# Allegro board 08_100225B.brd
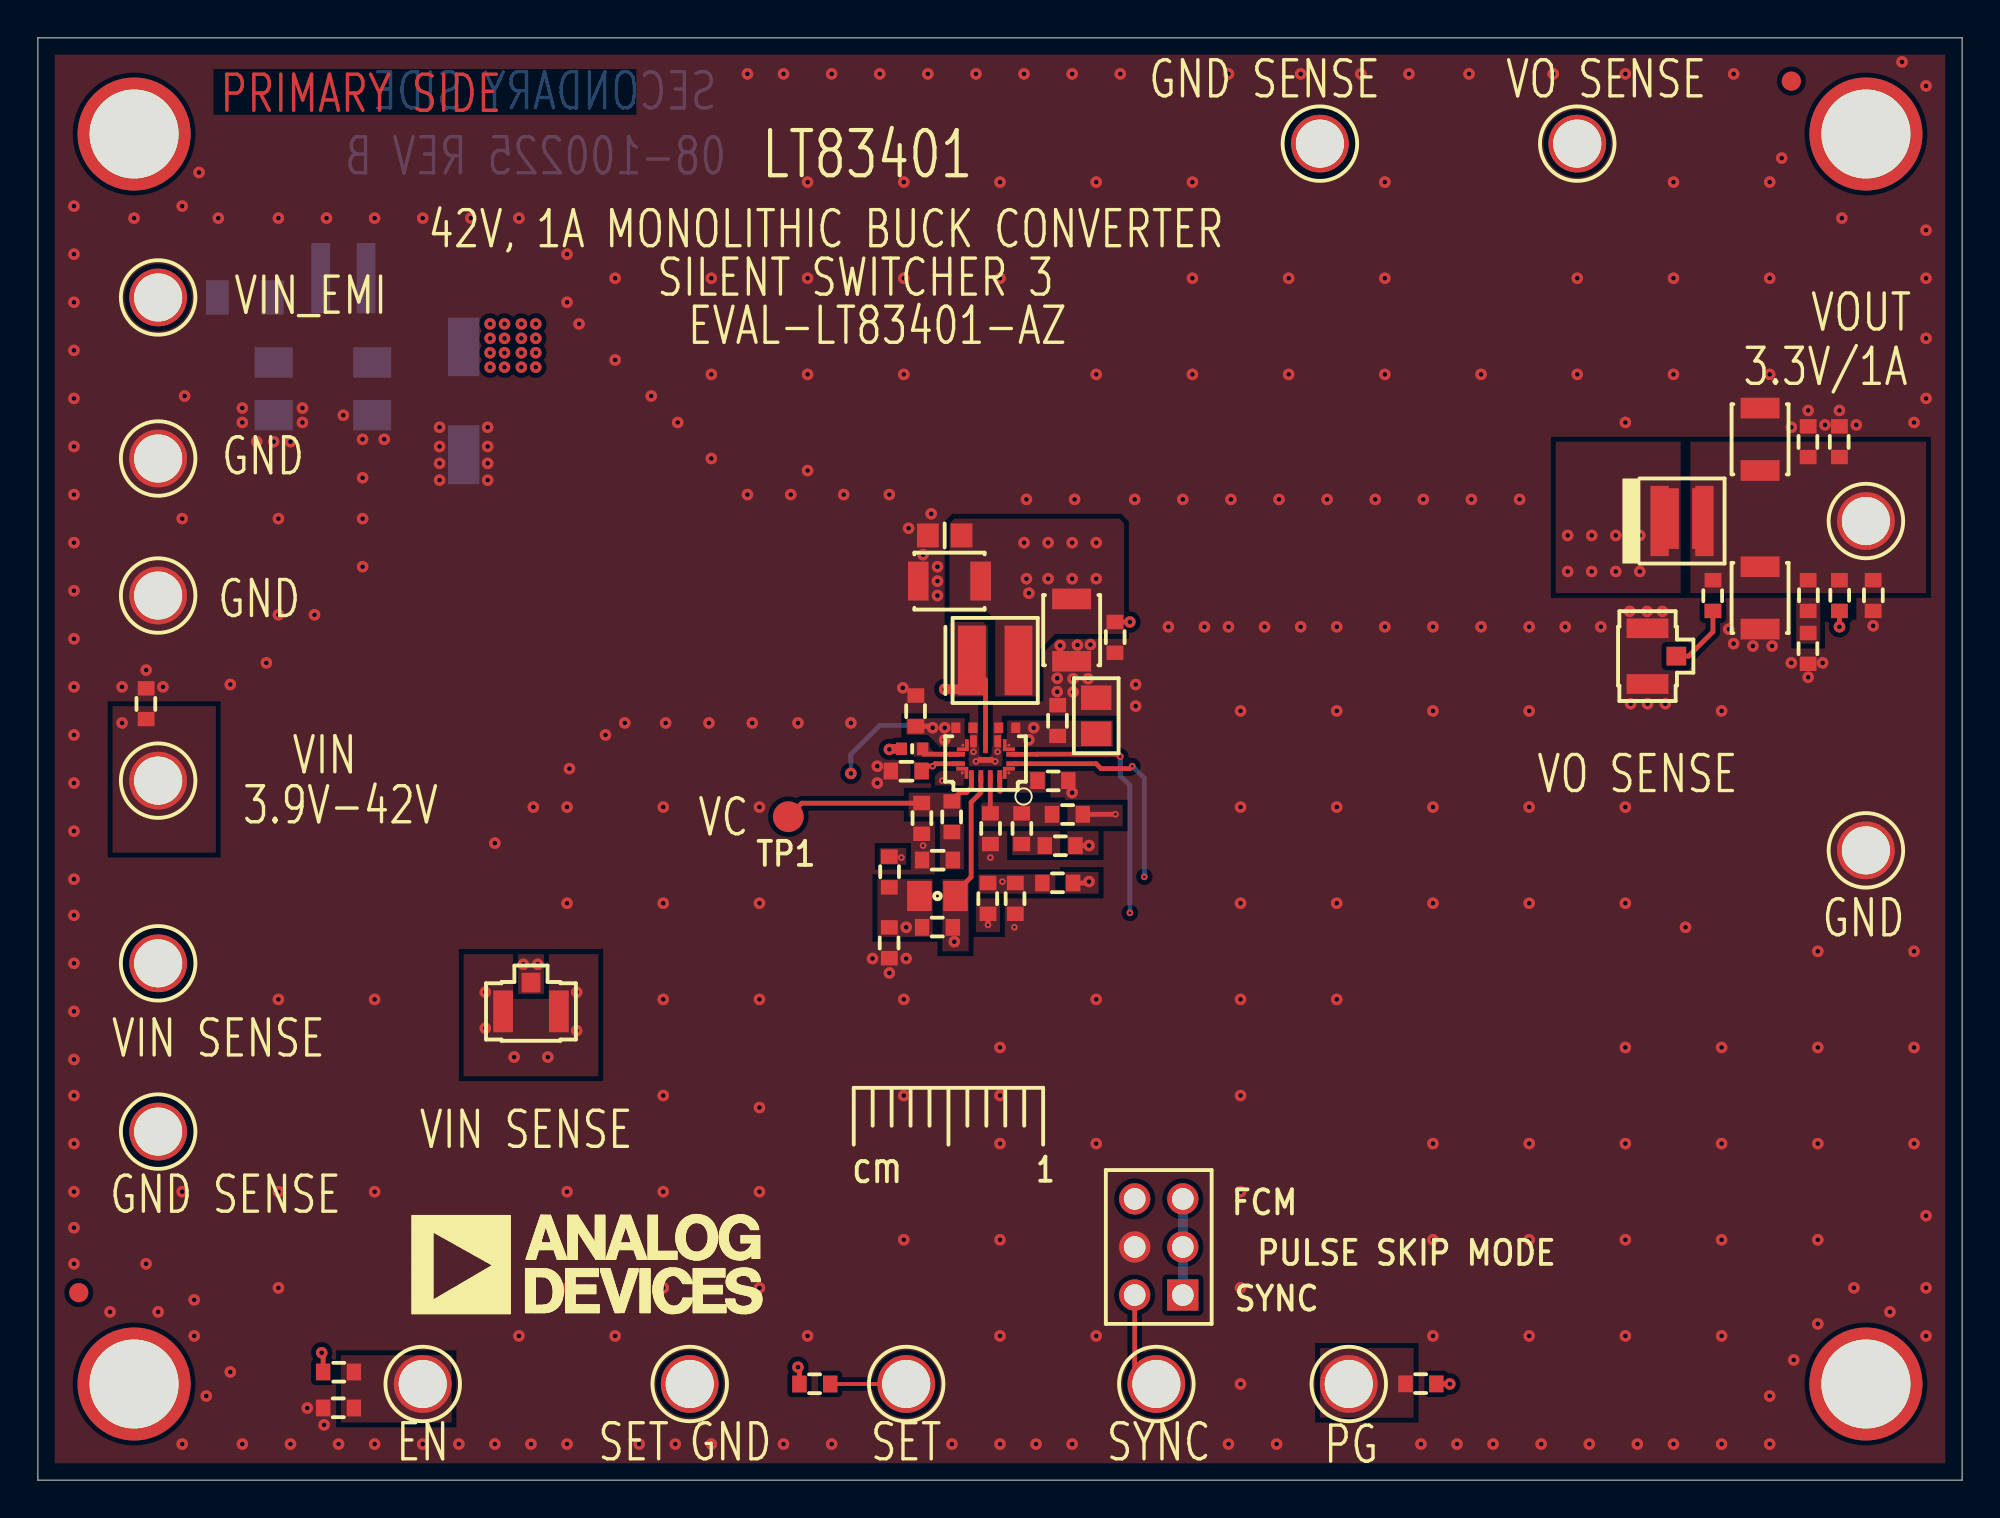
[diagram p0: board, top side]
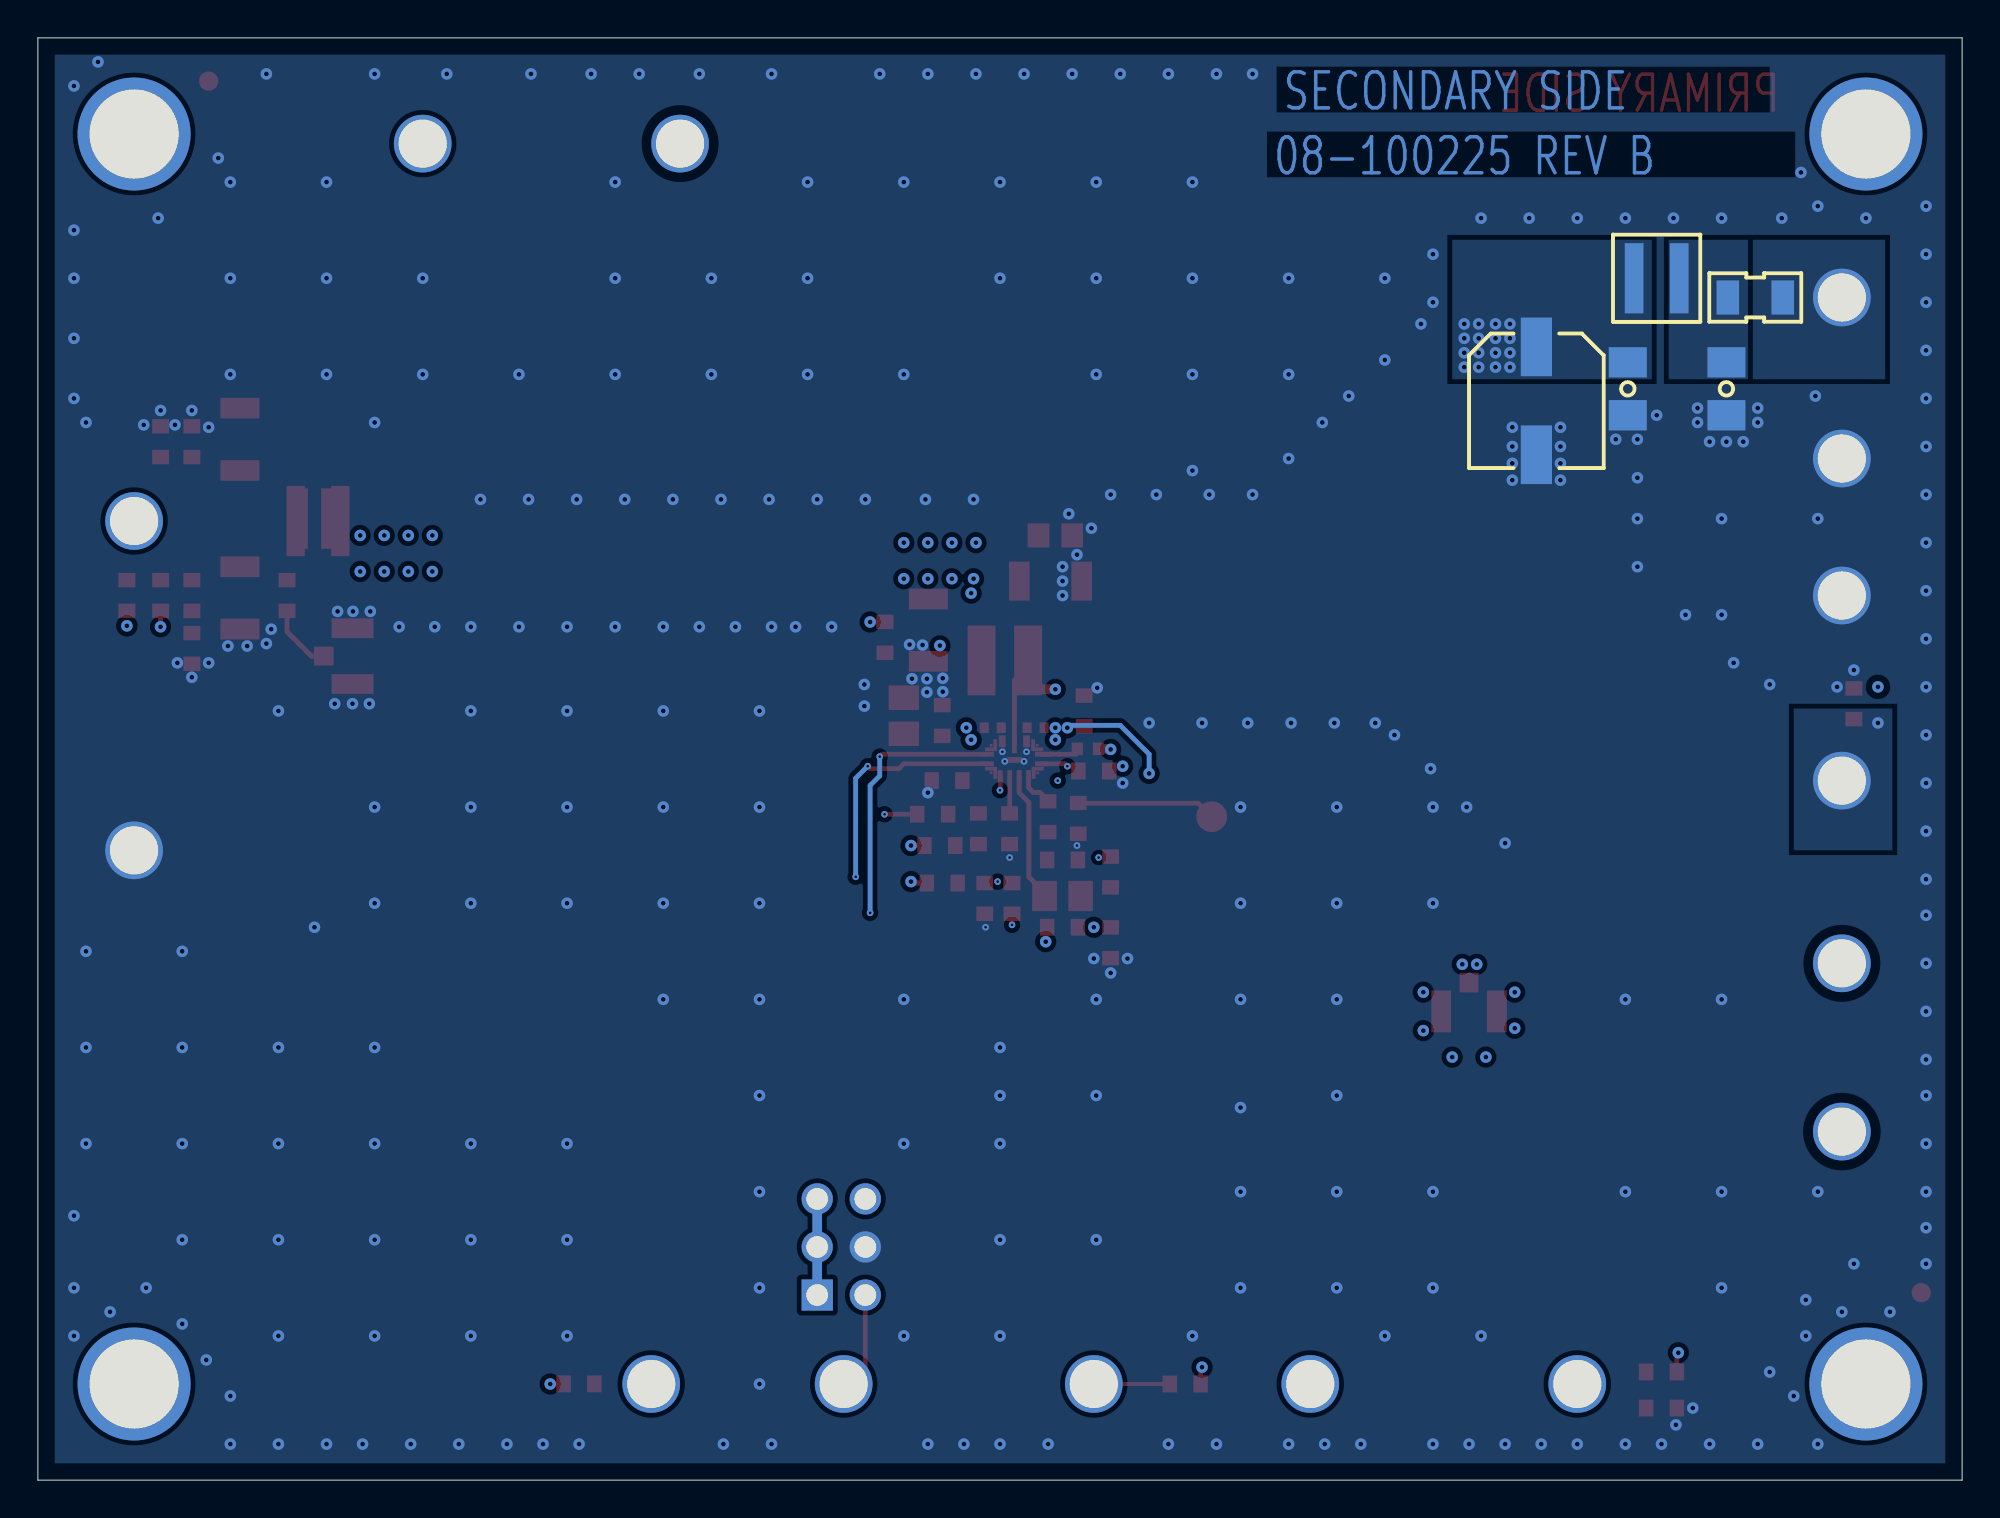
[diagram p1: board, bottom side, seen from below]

Outline 101.6 x 76.2 mm; copper layers: TOP, LAYER_2, LAYER_3, BOTTOM. Coordinates in mm from the lower left corner of the outline.
Outline path: 0,76.2 0,0 101.6,0 101.6,76.2 0,76.2

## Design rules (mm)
constraint set DEFAULT: min track width 0.203

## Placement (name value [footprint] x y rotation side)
C1  1uF  [C1206H71]  17.65 57.66 270 bottom
C2  2.2uF  [C0603]  5.71 41.02 90 top
C4  22uF  [CPLSMSQ260H315]  22.48 57.02 270 bottom
C5  4.7uF  [C0805H53]  55.88 40.39 90 top
C6  4.7uF  [C1206H71]  12.45 57.66 270 bottom
C7  1UF  [C0402]  51.18 39.75 180 top
C8  4700pF  [C0603]  47.5 32.77 180 top
C9  1UF  [C0402]  48.92 39.75 0 top
C10  2.2uF  [C0603]  56.87 44.53 270 top
C11  82PF  [C0603]  46.67 34.96 270 top
C12  1uF  [C0603]  45.85 37.47 180 top
C13  0.1uF  [C0402#2]  46.16 38.64 0 top
C14  1uF  [C0805H60]  47.5 30.86 180 top
C15  22uF  [C1210H106]  48.13 47.5 180 top
C16  22uF  [C1210H106]  54.58 44.91 270 top
C18  TBD0805  [C0805]  47.88 49.91 180 top
C19  22uF  [C1210H106]  90.93 54.99 90 top
C20  22uF  [C1210H106]  90.93 46.61 270 top
C21  2.2uF  [C0603]  96.9 46.74 270 top
C22  TBD0603  [C0603]  93.47 54.86 90 top
C23  TBD0603  [C0603]  95.12 54.86 90 top
C24  TBD0603  [C0603]  93.47 46.74 270 top
C25  1uF  [C0603]  46.35 40.64 90 top
C26  1uF  [C0603]  53.85 40.13 90 top
E1  2501-2-00-80-00-00-07-0  [CNMILLMAX2501]  6.35 62.48 90 top
E2  2501-2-00-80-00-00-07-0  [CNMILLMAX2501]  6.35 53.98 90 top
E3  2501-2-00-80-00-00-07-0  [CNMILLMAX2501]  6.35 27.3 90 top
E4  2501-2-00-80-00-00-07-0  [CNMILLMAX2501]  6.35 18.41 90 top
E5  2501-2-00-80-00-00-07-0  [CNMILLMAX2501]  59.05 5.08 0 top
E6  2501-2-00-80-00-00-07-0  [CNMILLMAX2501]  6.35 36.96 0 top
E7  2501-2-00-80-00-00-07-0  [CNMILLMAX2501]  6.35 46.74 0 top
E8  2501-2-00-80-00-00-07-0  [CNMILLMAX2501]  20.32 5.08 0 top
E9  2501-2-00-80-00-00-07-0  [CNMILLMAX2501]  69.22 5.08 0 top
E10  2501-2-00-80-00-00-07-0  [CNMILLMAX2501]  81.28 70.61 90 top
E11  2501-2-00-80-00-00-07-0  [CNMILLMAX2501]  67.69 70.61 270 top
E12  2501-2-00-80-00-00-07-0  [CNMILLMAX2501]  96.52 50.67 0 top
E13  2501-2-00-80-00-00-07-0  [CNMILLMAX2501]  96.52 33.27 0 top
E14  2501-2-00-80-00-00-07-0  [CNMILLMAX2501]  45.85 5.08 0 top
E15  2501-2-00-80-00-00-07-0  [CNMILLMAX2501]  34.42 5.08 0 top
FB1  800OHM AT 100MHZ  [L1206H71]  10.92 62.48 0 bottom
J5  RSP-122811-01  [CNSMASQ102H56]  26.04 24.77 180 top
J6  RSP-122811-01  [CNSMASQ102H56]  84.99 43.54 90 top
JP1  TSW-103-07-F-D  [CNSAMTEC2X3H330LD36]  60.45 9.78 90 top
L1  2.2UH  [LSMSQ157H83]  50.55 43.31 0 top
L2  4.7UH  [LSMSQ161H83]  16.13 63.5 0 bottom
L3  2.2UH  [LSMSQ157H122]  86.81 50.67 0 top
NOREF  -  []  0 76.2 0 top
NOREF#2  -  [unnamed#2]  5.08 71.12 0 top
NOREF#3  -  []  49.07 88.54 0 top
NOREF#4  -  []  0.64 75.56 270 top
NOREF#5  -  []  46.23 21.97 0 top
NOREF#6  -  [unnamed#2]  96.52 5.08 0 top
NOREF#7  -  []  -115.44 -203.45 0 top
NOREF#8  -  []  -73.41 -186.18 0 top
NOREF#9  -  [unnamed#2]  5.08 5.08 0 top
NOREF#10  -  []  0 0 90 top
NOREF#11  -  []  -73.41 -186.18 0 top
NOREF#12  -  []  100.97 75.56 180 top
NOREF#13  -  []  330.42 228.99 0 top
NOREF#14  -  []  337.44 165.48 0 top
NOREF#15  -  []  0.64 0.64 0 top
NOREF#16  -  [unnamed#2]  92.58 73.91 0 top
NOREF#17  -  []  165.48 219.71 0 top
NOREF#18  -  [unnamed#2]  2.16 9.91 0 top
NOREF#19  -  []  100.97 0.64 90 top
NOREF#20  -  [unnamed#2]  96.52 71.12 0 top
NOREF#21  -  []  262.51 65.15 0 top
R1  1K  [R0603]  48.26 35.05 270 top
R2  TBD0603  [R0603]  41.02 5.08 180 top
R3  100K  [R0603]  15.88 5.71 0 top
R4  47.5K  [R0603]  53.59 36.96 0 top
R5  TBD0603  [R0603]  15.88 3.81 180 top
R6  33.2K  [R0603]  47.5 29.21 180 top
R7  0  [R0603]  51.94 34.42 90 top
R8  0.001  [R0612]  87 50.8 0 top
R9  TBD0603  [R0603]  54.36 35.18 0 top
R10  280K  [R0603]  53.85 31.55 180 top
R11  49.9K  [R0603]  51.61 30.73 270 top
R12  100K  [R0603]  73.03 5.09 180 top
R13  TBD0603  [R0603]  93.47 43.94 270 top
R14  0  [R0603]  53.98 33.53 0 top
R15  TBD0603  [R0603]  50.29 34.42 90 top
R16  TBD0603  [R0603]  95.12 46.74 90 top
R17  TBD0603  [R0603]  44.96 32.13 90 top
R18  0  [R0603]  44.96 28.39 270 top
R19  TBD0603  [R0603]  50.16 30.73 270 top
R22  0  [R0603]  88.44 46.74 270 top
TP1  NCTARGET_PAD_C62AU  [TPSMC62]  39.62 35.05 0 top
U1  LT83401RUDB#TRPBF  [QFN15_CP-15-1]  50.04 38.1 180 top

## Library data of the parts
C1 = CAP: Tolerance: 10; User Part Number: UPN; alternate symbols: (C1206H71); part number: CAP_SM-1UF,50V,10,E030213,C1206H71; tolerance: 10
C2 = CAP: Tolerance: 10; User Part Number: UPN; alternate symbols: (C0603); part number: CAP_SM-2.2UF,50V,10,E024995,C0603; tolerance: 10
C4 = CAPP: Tolerance: 20; User Part Number: UPN; alternate symbols: (CPLSMSQ260H315); part number: CAPP_SM-22UF,63V,20,E033596,CPLSMSQ260H315; tolerance: 20
C5 = CAP: Tolerance: 10; User Part Number: UPN; alternate symbols: (C0805H53); part number: CAP_SM-4.7UF,50V,10,E028468,C0805H53; tolerance: 10
C6 = CAP: Tolerance: 10; User Part Number: UPN; alternate symbols: (C1206H71); part number: CAP_SM-4.7UF,50V,10,E026699,C1206H71; tolerance: 10
C7 C9 = CAP: User Part Number: UPN; Tolerance: 10; alternate symbols: (C0402L); part number: CAP_SM-1UF,50V,10,E064438,C0402; tolerance: 10
C8 = CAP: Tolerance: 10; User Part Number: UPN; alternate symbols: (C0603); part number: CAP_SM-4700PF,50V,10,E000427,C0603; tolerance: 10
C10 C21 = CAP: Tolerance: 10; User Part Number: UPN; alternate symbols: (C0603); part number: CAP_SM-2.2UF,25V,10,E031885,C0603; tolerance: 10
C11 = CAP: Tolerance: 5; User Part Number: UPN; alternate symbols: (C0603); part number: CAP_SM-82PF,50V,5,E042666,C0603; tolerance: 5
C12 = CAP: Tolerance: 10; User Part Number: UPN; alternate symbols: (C0603); part number: CAP_SM-1UF,25V,10,E033832,C0603; tolerance: 10
C13 = CAP: Tolerance: 10; User Part Number: UPN; alternate symbols: (C0402); part number: CAP_SM-0.1UF,50V,10,E028943,C0402; tolerance: 10
C14 = CAP: Tolerance: 10; User Part Number: UPN; alternate symbols: (C0805H60); part number: CAP_SM-1UF,50V,10,E030886,C0805H60; tolerance: 10
C15 C16 C19 C20 = CAP: Tolerance: 10; User Part Number: UPN; alternate symbols: (C1210H106); part number: CAP_SM-22UF,25V,10,E025745,C1210H106; tolerance: 10
C18 = CAP: User Part Number: UPN; alternate symbols: (C0805); part number: CAP_SM-TBD0805,TBD0805,TBD0805,E000383,C0805
C22-C24 = CAP: User Part Number: UPN; alternate symbols: (C0603); part number: CAP_SM-TBD0603,TBD0603,TBD0603,E000382,C0603
C25 C26 = CAP: Tolerance: 10; User Part Number: UPN; alternate symbols: (C0603); part number: CAP_SM-1UF,50V,10,E023087,C0603; tolerance: 10
E1-E15 = CNTP1P: User Part Number: UPN; Tolerance: N/A; alternate symbols: (CNMILLMAX2501); part number: CNTP1P_TH-2501-2-00-80-00-00-07-0,E031108,CNMILLMAX2501; tolerance: N/A
FB1 = FERRITE: User Part Number: UPN; Tolerance: 25; alternate symbols: (L1206H71); part number: FERRITE_SM-800OHM AT 100MHZ,25,E067875,L1206H71; tolerance: 25
J5 J6 = CNBNC3P: User Part Number: UPN; Tolerance: N/A; alternate symbols: (CNSMASQ102H56); part number: CNBNC3P_SM-RSP-122811-01,E033920,CNSMASQ102H56; tolerance: N/A
JP1 = CN6P_ODD_EVEN: Tolerance: N/A; User Part Number: UPN; alternate symbols: (CNSAMTEC2X3H330LD36); part number: CN6P_ODD_EVEN_TH-TSW-103-07-F-D,E031502,CNSAMTEC2X3H330LD36; tolerance: N/A
L1 = IND: User Part Number: UPN; Tolerance: 20; alternate symbols: (LSMSQ157H83); part number: IND_SM-2.2UH,20,E051506,LSMSQ157H83; tolerance: 20
L2 = IND: User Part Number: UPN; Tolerance: 20; alternate symbols: (LSMSQ161H83); part number: IND_SM-4.7UH,20,E046383,LSMSQ161H83; tolerance: 20
L3 = IND: User Part Number: UPN; Tolerance: 20; alternate symbols: (LSMSQ157H122); part number: IND_SM-2.2UH,20,E054929,LSMSQ157H122; tolerance: 20
R1 = RES: Tolerance: 1; User Part Number: UPN; alternate symbols: (R0603); part number: RES_SM-1K,E003678,1/10W,1,R0603; tolerance: 1
R2 R5 R9 R13 R15-R17 R19 = RES: User Part Number: UPN; alternate symbols: (R0603); part number: RES_SM-TBD0603,E004050,TBD0603,TBD0603,R0603
R3 R12 = RES: Tolerance: 1; User Part Number: UPN; alternate symbols: (R0603); part number: RES_SM-100K,E010279,1/10W,1,R0603; tolerance: 1
R4 = RES: Tolerance: 1; User Part Number: UPN; alternate symbols: (R0603); part number: RES_SM-47.5K,E032237,1/10W,1,R0603; tolerance: 1
R6 = RES: Tolerance: 1; User Part Number: UPN; alternate symbols: (R0603); part number: RES_SM-33.2K,E028266,1/10W,1,R0603; tolerance: 1
R7 R14 R18 R22 = RES: Tolerance: JUMPER; User Part Number: UPN; alternate symbols: (R0603); part number: RES_SM-0,E007502,1/10W,JUMPER,R0603; tolerance: JUMPER
R8 = RES: User Part Number: UPN; Tolerance: 1; alternate symbols: (R0612); part number: RES_SM-0.001,E065605,1W,1,R0612; tolerance: 1
R10 = RES: Tolerance: 1; User Part Number: UPN; alternate symbols: (R0603); part number: RES_SM-280K,E020071,1/10W,1,R0603; tolerance: 1
R11 = RES: Tolerance: 1; User Part Number: UPN; alternate symbols: (R0603); part number: RES_SM-49.9K,E015342,1/10W,1,R0603; tolerance: 1
TP1 = NC1P: Tolerance: N/A; User Part Number: UPN; alternate symbols: (TPSMC62); part number: NC1P_SM-NCTARGET_PAD_C62AU,E050423,TPSMC62; tolerance: N/A
U1 = ADLT83401: User Part Number: UPN; Tolerance: N/A; alternate symbols: (QFN15_CP-15-1); part number: ADLT83401_SM-LT83401RUDB#TRPBF,E072989,QFN15_CP-15-1; tolerance: N/A

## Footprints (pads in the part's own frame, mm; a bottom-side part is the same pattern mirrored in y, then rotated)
C0402
  rect 0.483x0.559 smd: 1(-0.45,0) 2(0.45,0)
C0402#2
  rect 0.584x0.66 smd: 1(-0.559,0) 2(0.559,0)
C0603
  rect 0.762x0.889 smd: 1(-0.813,0) 2(0.813,0)
C0805
  rect 1.143x1.27 smd: 1(-0.889,0) 2(0.889,0)
C0805H53
  rect 1.295x1.6 smd: 1(-0.953,0) 2(0.953,0)
C0805H60
  rect 1.295x1.6 smd: 1(-0.953,0) 2(0.953,0)
C1206H71
  rect 1.6x2.007 smd: 1(-1.397,0) 2(1.397,0)
C1210H106
  rect 1.092x2.057 smd: 1(-1.646,0) 2(1.646,0)
CNMILLMAX2501
  round 3.048 hole 2.54: 1(0,0)
CNSAMTEC2X3H330LD36
  rect 1.651x1.651 hole 1.143: 1(0,0)
  round 1.651 hole 1.143: 2(0,2.54) 3(2.54,0) 4(2.54,2.54) 5(5.08,0) 6(5.08,2.54)
CNSMASQ102H56
  rect 0.991x1.041 smd: 1(0,-1.521)
  rect 1.041x2.21 smd: 2(-1.471,0) 3(1.471,0)
CPLSMSQ260H315
  rect 3.099x1.651 smd: N(2.85,0) P(-2.85,0)
L1206H71
  rect 1.194x1.803 smd: 1(-1.45,0) 2(1.45,0)
LSMSQ157H83
  rect 1.473x3.683 smd: 1(-1.232,0) 2(1.232,0)
LSMSQ157H122
  rect 0.965x3.708 smd: 1(-1.181,0) 2(1.181,0)
LSMSQ161H83
  rect 0.991x3.708 smd: 1(-1.19,0) 2(1.19,0)
QFN15_CP-15-1
  custom 0.159x0.159 smd: 1(-1.229,0.729) 4(-1.229,-0.729) 8(1.2,-0.729) 11(1.229,0.729)
  rect 0.66x0.254 smd: 2(-1.42,0.25) 3(-1.42,-0.25) 9(1.42,-0.25) 10(1.42,0.25)
  rect 0.356x0.635 smd: 5(-0.64,-0.932) 7(0.64,-0.932)
  rect 0.254x0.94 smd: 6(0,-0.78)
  rect 0.254x0.66 smd: 12(0.75,0.92) 13(0.25,0.92) 14(-0.25,0.92) 15(-0.75,0.92)
  rect 0.813x0.305 smd: 16(0,0.051)
R0603
  rect 0.762x0.889 smd: 1(-0.813,0) 2(0.813,0)
R0612
  rect 0.94x3.2 smd: 1(-0.82,0) 2(0.82,0)
TPSMC62
  round 1.626 smd: 1(0,0)
unnamed#2
  round 5.969 hole 4.699 unplated: (0,0)

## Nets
GND_POWER: C1.2(N2) C2.2(N2) C4.N(N2) C5.2(N2) C6.2(N2) C7.2(N2) C8.2(N2) C9.2(N2) C10.2(N2) C11.2(N2) C12.2(N2) C15.2(N2) C16.2(N2) C18.2(N2) C19.2(N2) C20.2(N2) C21.2(N2) C22.2(N2) C23.2(N2) C25.2(N2) C26.2(N2) E2.1(N1) E4.1(N1) E7.1(N1) E11.1(N1) E13.1(N1) J5.2 J5.3(SH2) J6.2 J6.3(SH2) JP1.4 R4.2(N2) R5.2(N2) R11.2(N2) R13.2(N2) R15.1 R17.2(N2) R18.2(N2) U1.5 U1.7 U1.16
VIN: C1.1 C2.1 C4.P C5.1 C7.1 C9.1 C25.1 C26.1 E3.1(N1) E6.1(N1) J5.1 L2.2(N2) R3.1 U1.4 U1.8(VIN_2)
BST: C13.2(N2) U1.9
INTVCC: C12.1 JP1.6(N6) R19.2(N2) U1.10
OUTS: R7.2(N2) R9.1 R15.2(N2) U1.14
PG: E9.1(N1) R12.2(N2) U1.2
PGFB: R10.2(N2) R11.1 R19.1 U1.15
SET: C14.1 R2.2(N2) R6.1 U1.13
SW: C13.1 L1.1 U1.6
SYNC: JP1.1 JP1.3 JP1.5 U1.3
UNNAMED_2_ADLT83401_I247_RT: R4.1 U1.1
UNNAMED_2_CAP_I105_N2: C24.2(N2) R13.1
UNNAMED_2_CAP_I141_N1: C10.1 C15.1 C16.1 C18.1 E10.1(N1) L1.2(N2) L3.1 R8.1 R10.1 R14.2(N2)
UNNAMED_2_CAP_I218_N1: C6.1 FB1.2(N2) L2.1
UNNAMED_2_CAP_I232_N2: C14.2(N2) E15.1(N1) R6.2(N2) R17.1 R18.1
UNNAMED_2_CAP_I244_N1: C8.1 R1.2(N2)
UNNAMED_2_CN6PODDEVEN_I122_N2: E5.1(N1) JP1.2
UNNAMED_2_CNBNC3P_I240_CNTR: J6.1 R22.2(N2)
UNNAMED_2_CNTP1P_I204_N1: E1.1(N1) FB1.1
UNNAMED_2_CNTP1P_I209_N1: E8.1(N1) R3.2(N2) R5.1 U1.11
UNNAMED_2_CNTP1P_I231_N1: E14.1(N1) R2.1
UNNAMED_2_RES_I157_N1: R7.1 R14.1
UNNAMED_2_RES_I219_N2: R9.2(N2) R16.1
VC: C11.1 R1.1 TP1.1(N1) U1.12
VOUT: C19.1 C20.1 C21.1 C22.1 C23.1 C24.1 E12.1(N1) L3.2(N2) R8.2(N2) R12.1 R16.2(N2) R22.1

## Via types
v1: diameter 0.61, hole 0.254, TOP to BOTTOM, 394 vias
v2: diameter 0.356, hole 0.152, TOP to BOTTOM, 18 vias

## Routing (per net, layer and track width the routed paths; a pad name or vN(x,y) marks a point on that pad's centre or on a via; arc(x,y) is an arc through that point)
GND_POWER: length 205.9
  TOP w0.254: 10.1,41.97 v1(10.16,42.04)
  LAYER_3 w0.254: v1(96.9,45.14) 96.39,44.63 96.39,42.42 87.5,33.53 57.66,33.53 57.02,32.89 57.02,31.37 56.13,30.48 49.78,30.48 47.37,32.89 v2(45.59,32.89) ; v1(44.32,37.72) 43.94,38.1 42.42,38.1 40.13,35.81 40.13,24.13 34.42,18.41 E4.1 ; E11.1 74.17,70.61 75.06,69.72 75.06,63.37 72.9,61.21 54.36,61.21 49.66,56.52 49.66,47.88 53.44,44.09 v1(53.98,44.09) ; v1(4.45,41.91) 2.79,40.26 2.79,32.38 4.32,30.86 23.37,30.86 24.77,29.46 24.77,27.56
  vias: v1(1.91,67.31) v1(1.91,64.77) v1(1.91,62.23) v1(1.91,59.69) v1(1.91,57.15) v1(1.91,54.61) v1(1.91,52.07) v1(1.91,49.53) v1(1.91,46.99) v1(1.91,44.45) v1(1.91,41.91) v1(1.91,39.37) v1(1.91,36.83) v1(1.91,34.29) v1(1.91,31.75) v1(1.91,29.84) v1(1.91,27.3) v1(1.91,24.77) v1(1.91,22.23) v1(1.91,20.32) v1(1.91,17.78) v1(1.91,15.24) v1(1.91,13.34) v1(1.91,11.43) v1(3.81,8.89) v1(5.08,66.67) v1(5.71,42.8) v1(5.71,11.43) v1(6.35,8.89) v1(6.6,41.91) v1(7.62,67.31) v1(7.62,50.8) v1(7.62,15.24) v1(7.62,1.91) v1(7.75,57.28) v1(8.26,9.53) v1(8.26,7.62) v1(8.51,69.09) v1(8.89,4.45) v1(9.53,66.67) v1(10.16,5.71) v1(10.79,56.64) v1(10.79,55.88) v1(10.79,1.91) v1(11.56,54.86) v1(12.06,43.18) v1(12.45,54.86) v1(12.7,66.67) v1(12.7,50.8) v1(12.7,45.72) v1(12.7,25.4) v1(12.7,15.24) v1(12.7,10.16) v1(13.34,54.86) v1(13.34,1.91) v1(13.97,56.64) v1(13.97,55.88) v1(14.22,3.81) v1(14.61,45.72) v1(15.11,2.92) v1(15.24,66.67) v1(15.88,1.91) v1(16.13,56.26) v1(17.14,54.99) v1(17.14,52.96) v1(17.14,50.8) v1(17.14,48.26) v1(17.78,66.67) v1(17.78,25.4) v1(17.78,15.24) v1(17.78,1.91) v1(18.29,54.99) v1(20.32,66.67) v1(20.32,1.91) v1(21.21,55.63) v1(21.21,54.61) v1(21.21,53.72) v1(21.21,52.83) v1(22.23,1.91) v1(22.86,66.67) v1(23.62,25.78) v1(23.62,23.88) v1(23.75,55.63) v1(23.75,54.61) v1(23.75,53.72) v1(23.75,52.83) v1(24.13,33.66) v1(24.13,1.91) v1(25.15,22.35) v1(25.4,66.67) v1(25.4,7.62) v1(26.04,1.91) v1(26.16,35.56) v1(26.92,22.35) v1(27.94,64.77) v1(27.94,62.23) v1(27.94,35.56) v1(27.94,30.48) v1(27.94,15.24) v1(27.94,10.16) v1(27.94,1.91) v1(28.07,37.59) v1(28.45,25.78) v1(28.45,23.75) v1(28.57,61.09) v1(29.97,39.37) v1(30.48,63.5) v1(30.48,59.18) v1(30.48,7.62) v1(30.99,40.01) v1(31.75,1.91) v1(32.38,57.28) v1(33.02,35.56) v1(33.02,30.48) v1(33.02,25.4) v1(33.02,20.32) v1(33.02,15.24) v1(33.02,10.16) v1(33.15,40.01) v1(33.66,1.91) v1(33.78,55.88) v1(35.43,40.01) v1(35.56,63.5) v1(35.56,58.42) v1(35.56,53.98) v1(35.56,1.91) v1(37.47,74.3) v1(37.47,52.07) v1(37.72,40.01) v1(38.1,35.56) v1(38.1,30.48) v1(38.1,25.4) v1(38.1,19.68) v1(38.1,15.24) v1(38.1,10.16) v1(39.37,74.3) v1(39.37,1.91) v1(39.75,52.07) v1(40.13,40.01) v1(40.64,68.58) v1(40.64,63.5) v1(40.64,58.42) v1(40.64,53.34) v1(40.64,7.62) v1(41.91,74.3) v1(41.91,1.91) v1(42.55,52.07) v1(42.93,40.01) v1(44.07,27.56) v1(44.32,36.83) v1(44.45,74.3) v1(44.96,52.07) v1(44.96,26.8) v1(45.72,68.58) v1(45.72,63.5) v1(45.72,58.42) v1(45.67,41.86) v1(45.72,25.4) v1(45.72,20.32) v1(45.72,12.7) v1(45.85,27.56) v1(45.97,50.29) v1(46.74,48.9) v1(46.99,74.3) v1(47.17,51.05) v1(47.5,48.26) v1(47.5,47.5) v1(47.5,46.74) v1(48.26,1.91) v1(49.53,74.3) v1(50.8,68.58) v1(50.8,63.5) v1(50.8,22.86) v1(50.8,20.32) v1(50.8,17.78) v1(50.8,12.7) v1(50.8,7.62) v1(50.8,1.91) v1(52.07,74.3) v1(52.2,51.82) v1(52.7,1.91) v1(53.82,42.37) v1(53.82,41.66) v1(54.61,74.3) v1(54.61,36.32) v1(54.61,1.91) v1(54.74,51.82) v1(54.66,42.34) v1(54.66,41.63) v1(54.89,44.12) v1(55.45,42.34) v1(55.58,44.15) v1(55.88,68.58) v1(55.88,58.42) v1(55.88,25.4) v1(55.88,17.78) v1(55.88,7.62) v1(57.15,74.3) v1(57.91,51.82) v1(57.96,42.04) v1(57.96,40.89) v1(59.69,45.09) v1(60.45,51.82) v1(60.96,68.58) v1(60.96,63.5) v1(60.96,58.42) v1(61.59,45.09) v1(62.87,74.3) v1(62.87,45.09) v1(62.87,1.91) v1(62.99,51.82) v1(63.5,40.64) v1(63.5,35.56) v1(63.5,30.48) v1(63.5,25.4) v1(63.5,20.32) v1(63.5,15.24) v1(63.5,10.16) v1(63.5,5.08) v1(64.77,45.09) v1(65.41,1.91) v1(65.53,51.82) v1(66.04,63.5) v1(66.04,58.42) v1(66.67,74.3) v1(66.67,45.09) v1(68.07,51.82) v1(68.58,45.09) v1(68.58,40.64) v1(68.58,35.56) v1(68.58,30.48) v1(68.58,25.4) v1(69.85,74.3) v1(70.61,51.82) v1(71.12,68.58) v1(71.12,63.5) v1(71.12,58.42) v1(71.12,45.09) v1(72.39,74.3) v1(73.03,1.91) v1(73.15,51.82) v1(73.66,45.09) v1(73.66,40.64) v1(73.66,35.56) v1(73.66,30.48) v1(73.66,17.78) v1(73.66,12.7) v1(73.66,7.62) v1(74.93,1.91) v1(75.56,74.3) v1(75.69,51.82) v1(76.2,58.42) v1(76.2,45.09) v1(76.83,1.91) v1(78.23,51.82) v1(78.74,45.09) v1(78.74,40.64) v1(78.74,35.56) v1(78.74,30.48) v1(78.74,17.78) v1(78.74,12.7) v1(78.74,7.62) v1(79.38,1.91) v1(80.01,74.3) v1(80.64,45.09) v1(81.28,63.5) v1(81.28,58.42) v1(81.92,1.91) v1(82.52,45.09) v1(83.82,74.3) v1(83.82,55.88) v1(83.82,35.56) v1(83.82,30.48) v1(83.82,22.86) v1(83.82,17.78) v1(83.82,12.7) v1(83.82,7.62) v1(84.05,45.9) v1(84.1,41.02) v1(84.45,1.91) v1(84.96,45.9) v1(84.99,41.02) v1(85.78,45.9) v1(85.93,41.02) v1(86.36,68.58) v1(86.36,63.5) v1(86.36,58.42) v1(86.36,1.91) v1(87,29.21) v1(88.9,40.64) v1(88.9,22.86) v1(88.9,17.78) v1(88.9,12.7) v1(88.9,7.62) v1(88.9,1.91) v1(89.28,44.96) v1(89.53,74.3) v1(89.53,44.2) v1(90.55,44.07) v1(91.44,68.58) v1(91.44,63.5) v1(91.44,58.42) v1(91.44,4.45) v1(91.44,1.91) v1(91.57,44.07) v1(92.08,69.85) v1(92.58,55.63) v1(92.58,43.18) v1(92.71,6.35) v1(93.47,56.52) v1(93.47,42.42) v1(93.98,27.94) v1(93.98,22.86) v1(93.98,17.78) v1(93.98,12.7) v1(93.98,8.26) v1(94.23,43.18) v1(94.36,55.75) v1(95.12,56.52) v1(95.25,66.67) v1(95.89,10.16) v1(96.01,55.75) v1(97.79,8.89) v1(98.42,74.93) v1(99.06,55.88) v1(99.06,27.94) v1(99.06,22.86) v1(99.06,17.78) v1(99.69,73.66) v1(99.69,66.04) v1(99.69,63.5) v1(99.69,60.33) v1(99.69,57.15) v1(99.69,13.97) v1(99.69,10.16) v1(99.69,7.62) v2(46.74,33.53) v2(49.4,38.48) v2(49.53,37.97) v2(50.29,32.89) v2(50.55,37.97) v2(50.67,38.48) v2(51.56,29.21)
VIN: length 151.1
  TOP w0.254: v1(14.99,6.73) 15.06,6.65 R3.1 ; v1(47.24,39.75) 47.17,39.83 C25.1
  LAYER_3 w0.254: v1(4.45,40.01) 3.3,38.86 3.3,32.77 4.57,31.5 23.75,31.5 25.4,29.84 25.4,27.48 v1(25.63,27.25) ; 45.2,39.51 44.84,39.51 43.94,38.61 42.16,38.61 39.62,36.07 39.62,24.38 34.16,18.92 10.67,18.92 6.35,23.24 E3.1 ; v1(14.99,6.73) 24.51,16.26 36.58,16.26 41.4,21.08 41.4,35.81 v1(42.93,37.34) ; 47.88,38.99 v1(47.88,39.12)
  BOTTOM w0.254: v1(42.93,37.34) 42.93,38.35 44.45,39.88 47.12,39.88 v1(47.24,39.75)
  vias: v1(23.88,61.09) v1(23.88,60.33) v1(23.88,59.56) v1(23.88,58.8) v1(24.64,61.09) v1(24.64,60.33) v1(24.64,59.56) v1(24.64,58.8) v1(25.53,61.09) v1(25.53,60.33) v1(25.53,59.56) v1(25.53,58.8) v1(26.29,61.09) v1(26.29,60.33) v1(26.29,59.56) v1(26.29,58.8) v1(26.39,27.25) v1(47.88,39.75) v1(52.32,39.12) v1(52.58,39.75)
BST: length 1.9
  TOP w0.254: 46.76,38.35 48.16,38.35 48.16,38.35 U1.9
INTVCC: length 35.8
  TOP w0.254: R19.2 v2(50.16,29.34) ; C12.1 46.91,37.72 v2(47.24,37.72) 47.38,37.85 U1.10
  LAYER_3 w0.254: v2(47.24,37.72) 48.13,37.72 48.39,37.47 48.39,36.58 47.88,36.07 45.85,36.07 44.83,35.05 44.83,32.64 45.47,32 46.74,32 49.4,29.34 v2(50.16,29.34) 57.91,21.59 JP1.6
OUTS: length 1.9
  TOP w0.254: 50.29,35.31 U1.14
PG: length 43.9
  TOP w0.25: U1.2 55.88,37.85 56.13,37.59
  TOP w0.254: v2(57.78,37.72) 57.66,37.59 56.13,37.59
  LAYER_3 w0.254: v2(58.42,31.88) 69.22,21.08 E9.1
  BOTTOM w0.254: v2(58.42,31.88) 58.42,37.08 v2(57.78,37.72)
PGFB: length 5.6
  TOP w0.254: v2(50.8,36.45) 50.79,36.46 U1.15
  LAYER_3 w0.254: v2(50.8,36.45) 50.93,36.32 v2(50.93,31.62)
SET: length 33.9
  TOP w0.254: 48.4,30.99 49.28,31.87 49.28,35.81 49.79,36.33 U1.13 ; R2.2 40.21,5.89 v1(40.13,5.97)
  LAYER_3 w0.254: v1(40.13,5.97) 39.75,6.35 39.75,10.16 48.39,18.8 v1(48.39,28.45)
SW: length 14.2
  TOP w0.254: U1.6 50.04,42.29
  TOP w0.508: v1(44.96,38.61) 44.99,38.64 C13.1 ; v1(47.88,41.78) 49.36,41.78
  LAYER_3 w0.254: v1(44.96,38.61) 45.21,38.35 48.26,38.35 49.6,39.7 49.6,40.95 48.77,41.78 v1(47.88,41.78)
SYNC: length 35.6
  TOP w0.25: U1.3 52.75,38.35 52.75,38.35 56.97,38.35 56.98,38.35 57.03,38.35 v2(57.15,38.23)
  LAYER_3 w0.254: JP1.5 60.45,27.18 v2(57.66,29.97)
  BOTTOM w0.254: v2(57.15,38.23) 57.15,37.21 57.66,36.7 v2(57.66,29.97)
  BOTTOM w0.508: JP1.1 JP1.5
UNNAMED_2_CAP_I141_N1: length 82.5
  TOP w0.254: C10.1 v1(57.66,45.34) ; R10.1 55.42,31.55 v1(55.5,31.62) ; R14.2 v1(55.5,33.53)
  LAYER_3 w0.254: v1(55.5,33.53) 55.5,40.13 56.39,41.02 56.39,47.12 ; v1(55.5,31.62) 56.26,32.38 56.26,39.75 57.02,40.51 57.02,44.7 v1(57.66,45.34) ; E10.1 76.71,70.61 75.56,69.47 75.56,63.12 73.15,60.71 54.61,60.71 50.16,56.26 50.16,48.13 51.44,46.86 v1(52.32,46.86)
  vias: v1(52.07,49.53) v1(52.2,47.62) v1(53.34,49.53) v1(53.34,47.62) v1(54.61,49.53) v1(54.61,47.62) v1(55.88,49.53) v1(55.88,47.62) v1(80.77,49.91) v1(80.77,48.01) v1(82.04,49.91) v1(82.04,48.01) v1(83.31,49.91) v1(83.31,48.01) v1(84.58,49.91) v1(84.58,48.01)
UNNAMED_2_CAP_I232_N2: length 32.6
  LAYER_3 w0.254: v1(45.85,29.21) 46.23,29.21 47.75,27.69 47.75,19.05 39.24,10.54 39.24,6.6 37.72,5.08 E15.1
UNNAMED_2_CN6PODDEVEN_I122_N2: length 5.4
  TOP w0.254: JP1.2 57.91,5.84 58.67,5.08 E5.1
UNNAMED_2_CNBNC3P_I240_CNTR: length 3.6
  TOP w0.254: J6.1 87.16,43.54 88.44,44.82 R22.2
UNNAMED_2_CNTP1P_I209_N1: length 51.2
  LAYER_3 w0.254: v2(47.75,36.96) 45.49,36.98 42.67,34.16 42.67,18.03 37.97,13.34 26.67,13.34 20.32,6.99 E8.1
UNNAMED_2_CNTP1P_I231_N1: length 4
  TOP w0.203: E14.1 R2.1
UNNAMED_2_RES_I219_N2: length 48.6
  TOP w0.254: v1(95.12,45.09) R16.1 ; R9.2 v2(56.9,35.18)
  LAYER_3 w0.254: v2(56.9,35.18) 56.9,34.8 57.66,34.04 87.25,34.04 95.89,42.67 95.89,44.45 95.25,45.09 v1(95.12,45.09)
VC: length 9.2
  TOP w0.254: 46.67,35.76 40.33,35.76 TP1.1 ; U1.12 49.29,36.59 49.03,36.33 48.69,36.33 48.26,35.9
VOUT: length 67
  TOP w0.254: R12.1 74.54,5.09 v1(74.55,5.08)
  LAYER_3 w0.254: E12.1 97.03,50.67 100.08,47.62 100.08,16.38 88.77,5.08 v1(74.55,5.08)

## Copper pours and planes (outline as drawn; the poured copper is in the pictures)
GND_POWER on TOP: 0.89,75.31 100.71,75.31 100.71,0.89 0.89,0.89 ; 7 cut-outs
GND_POWER on TOP: 44.45,33.4 44.45,32.51 45.85,32.51 45.85,33.4
GND_POWER on TOP: 22.48,27.79 22.48,21.34 29.59,21.34 29.59,27.79
GND_POWER on BOTTOM: 0.89,75.31 100.71,75.31 100.71,0.89 0.89,0.89 ; 14 cut-outs
GND_POWER on LAYER_2: 0.89,75.31 100.58,75.31 100.58,0.89 0.89,0.89 ; 14 cut-outs
GND_POWER on LAYER_3: 0.89,75.31 100.71,75.31 100.71,0.89 0.89,0.89 ; 12 cut-outs
GND_POWER on LAYER_3: 22.23,27.81 22.23,20.83 29.84,20.83 29.84,27.81
VIN on TOP: 45.85,40.26 48.95,40.26 48.95,38.73 47.62,38.73 46.99,39.37 45.85,39.37
VIN on TOP: 3.94,40.89 3.94,33.15 9.4,33.15 9.4,40.89
VIN on TOP: 25.35,27.79 25.35,25.68 26.72,25.68 26.72,27.79
VIN on TOP: 51.16,38.73 56.77,38.73 56.77,40.13 51.16,40.13
VIN on BOTTOM: 16.38,65.53 16.38,58.17 26.92,58.17 26.92,65.53
VIN on BOTTOM: 3.68,40.77 3.68,33.27 8.89,33.27 8.89,40.77
VIN on LAYER_3: 19.18,61.59 26.54,61.59 37.47,50.67 46.23,50.67 52.96,43.94 52.96,38.99 52.7,38.73 51.44,38.73 51.18,38.99 49.02,38.99 48.77,38.73 45.59,38.73 43.43,40.89 29.21,40.89 21.46,33.15 5.84,33.15 4.45,34.54 4.45,39.12 6.35,41.02 11.94,41.02 19.18,48.26
VIN on LAYER_3: 25.15,27.81 25.15,25.65 26.8,25.65 26.8,27.81
INTVCC on TOP: 49.53,30.73 49.53,28.96 50.8,28.96 50.8,30.73
OUTS on TOP: 49.78,35.69 49.78,34.54 53.98,34.54 53.98,35.81 49.91,35.81
PG on TOP: 67.69,6.99 67.69,3.3 72.64,3.3 72.64,6.99
PGFB on TOP: 49.66,32 49.66,30.99 53.72,30.99 53.72,32
SET on TOP: 47.75,31.75 47.75,27.94 49.15,27.94 49.15,31.75
SW on TOP: 48.13,45.34 48.13,41.4 50.16,41.4 50.16,45.09 49.91,45.34
UNNAMED_2_ADLT83401_I247_RT on TOP: 51.18,37.47 53.21,37.47 53.21,36.32 51.18,36.32
UNNAMED_2_CAP_I105_N2 on TOP: 92.84,46.61 92.84,44.2 94.11,44.2 94.11,46.61
UNNAMED_2_CAP_I141_N1 on TOP: 48.13,50.55 48.13,45.85 50.16,45.85 50.55,45.47 50.55,41.4 52.83,41.4 52.83,43.81 53.72,44.7 57.35,44.7 57.35,50.55 57.1,50.8 48.39,50.8
UNNAMED_2_CAP_I141_N1 on TOP: 54.36,34.29 54.36,33.02 56.01,33.02 56.01,34.29
UNNAMED_2_CAP_I141_N1 on TOP: 54.23,32.13 54.23,30.99 56.01,30.99 56.01,32.13
UNNAMED_2_CAP_I141_N1 on TOP: 80.14,54.86 80.14,46.86 86.74,46.86 86.74,54.86
UNNAMED_2_CAP_I141_N1 on LAYER_3: 51.56,50.8 51.56,46.74 51.94,46.35 85.72,46.35 85.72,50.8
UNNAMED_2_CAP_I218_N1 on BOTTOM: 11.3,65.53 11.3,58.17 15.49,58.17 15.49,65.53
UNNAMED_2_CAP_I232_N2 on TOP: 44.32,31.75 47.24,31.75 47.24,28.7 44.32,28.7
UNNAMED_2_CAP_I244_N1 on TOP: 47.62,34.67 47.62,32.26 48.9,32.26 48.9,34.67
UNNAMED_2_CNTP1P_I204_N1 on BOTTOM: 4.06,65.53 4.06,58.17 11.05,58.17 11.05,65.53
UNNAMED_2_CNTP1P_I209_N1 on TOP: 16,6.6 16,3.05 21.84,3.05 21.84,6.6
UNNAMED_2_CNTP1P_I209_N1 on TOP: 47.37,37.21 47.37,36.7 48.9,36.7 48.9,37.47 47.62,37.47
UNNAMED_2_RES_I157_N1 on TOP: 51.44,34.29 51.44,33.02 53.98,33.02 53.98,34.29
UNNAMED_2_RES_I219_N2 on TOP: 54.36,35.69 54.36,34.54 57.28,34.54 57.28,35.69
VC on TOP: 45.97,36.32 45.97,35.05 48.77,35.05 48.77,36.32
VOUT on TOP: 87.25,46.86 99.69,46.86 99.69,54.86 87.25,54.86

Small or netless copper shapes (teardrops, artwork), in the pictures only: 1 on TOP

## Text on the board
BOTTOM: SECONDARY SIDE | 08-100225 REV B
User.Comments: XXX | C | FOR JP1: INSTALL SHUNT ACROSS PIN5 AND PIN6. | 5.    INSTALL INDUCTORS L1 AS SHOWN BELOW. | FOOTPRINT | PIN1 INDICATOR | PCB : SECONDARY | PCB : PRIMARY | PART | TURRETS
TOP: PRIMARY SIDE
Ref Des/Silkscreen Top: FCM | SYNC | PULSE SKIP MODE | 42V, 1A MONOLITHIC BUCK CONVERTER | SILENT SWITCHER 3 | EVAL-LT83401-AZ | VIN SENSE | GND SENSE | GND | VIN_EMI | VIN | 3.9V-42V | EN | SET GND | VC | SET | PG | VO SENSE | 3.3V/1A | VOUT | LT83401
PAGE_OUTLINE: B | INITIAL RELEASE | PER ECR-128444 | 05NOV25 | 1 | CCORREA | EVAL-LT83401-AZ | -100225
BODY_CENTER: FAB NOTES REVISION: NOVEMBER 21 2022 | 8.   IMPEDANCE REQUIREMENTS: IF NO STACKUP IS DEFINED, THE VENDOR IS ALLOWED TO ADJUST THE DIELECTRIC | 13.  PLATING SPECIFICATION: | 1.   DIMENSIONS ARE IN INCHES (EXCEPT WHERE NOTED). | ALL DOCUMENTS & SPECIFICATIONS REFERRED TO BELOW SHOULD BE THE LATEST REVISIONS. | 2.  BOARD MATERIAL:(USE CHECKED ITEMS) | 3.   ALL LAMINATES & BONDING MATERIALS SHOULD BE SELECTED FROM IPC-4101 OR IPC-4103,(TG>170 DEGC TD>300 DEGC) | 4.   REFER TO IPC-6010 SERIES, CLASS 2 FOR FABRICATION. | 5.   REFER TO LAMINATION DIAGRAM FOR OVERALL BOARD THICKNESS, TOLERANCE APPLIES AFTER ALL LAMINATION AND PLATING | 6.   BOW & TWIST NOT TO EXCEED 0.0075 INCHES (0.75%) PER LINEAR INCH AND SHOULD BE MEASURED PER IPC-TM-650, METHOD 2.4.22. | 7.   ACCEPTABILITY PER ADI SPECIFICATION TST00115. | 9.   FILLET OPTIONS TO ENHANCE RELIABILITY AT PAD JUNCTIONS WHERE SPACING PERMITS. | 10.  THIEVING: | 11.  LAYER TO LAYER REGISTRATION SHALL BE WITHIN 0.003 INCHES. | 12.  DRILL SIZES ARE FINISHED HOLE SIZES. ALL HOLES SHALL BE LOCATED WITHIN 0.005 INCHES DTP,UNLESS SPECIFIED. | 14.  SURFACE FINISH: | 15.  SOLDERMASK: | 16.  APPLY SILKSCREEN TO BOTH SIDES USING A NON-CONDUCTIVE, EPOXY BASED INK PER ARTWORK. | (X) WHITE | ( ) OTHER | PROCESSES. FINISHED THICKNESS MEASURED FROM TOP COPPER TO BOTTOM COPPER. | (X)  ISOLA 370HR OR S1000-2 OR IT180 OR EQUIVALENT | ( )  ISOLA-FR408HR OR EQUIVALENT | ( )  ISOLA IS410 | ( )  MEGTRON 6 | ( )  NELCO-4000-13 | ( )  ROGERS 4350B | ( ) ROGERS 3003 | ( ) ARLON 85N | ( ) EM370D | ( )  OTHER ________________________ | ( ) FILLETS ALLOWED | (X) FILLETS NOT ALLOWED | ( ) VENDOR MAY ADD THIEVING TO COMPENSATE FOR LOW COPPER DENSITY AREAS MAINTAINING A MINIMUM | ( ) VENDOR MAY NOT ADD THIEVING TO COMPENSATE FOR LOW COPPER DENSITY AREAS. | (X) LPI | ( ) OTHER_________ | COLOR | (X) GREEN | HINDER PROPER SOLDER WICKING. BARREL RELIEF ON SOLDERMASK ALLOWED IN UNFILLED VIA IN PAD HOLES. | (X) REFER TO LAMINATION DIAGRAM FOR FINISHED COPPER WEIGHT/THICKNESS REQUIRMENTS | (X) IMMERSION GOLD (ENIG) 1.58-3.94 MICRO INCHES OVER 118-236 MICRO INCHES MIN. OF ELECTROLESS NICKEL PER IPC-4552 | ( ) OSP (ORGANIC SOLDERABILITY PRESERVATIVE) | ( ) IMMERSION SILVER | ( ) SOFT WIRE BONDABLE GOLD 30-50 MICRO INCHES OF SOFT WIRE | ( ) EDGE CONNECTOR FINGERS ARE TO BE PLATED WITH 100 MICRO-INCHES(.0001") OF LOW STRESS | THICKNESS & TRACE WIDTHS TO MEET THE IMPEDANCE REQUIREMENT. IF SPECIFIED, THE VENDOR MUST | TRACE WIDTH & SPACING THAT IMPACT THE REQUIREMENTS MUST HAVE WRITTEN APPROVAL FROM ADI. | MINIMUM BARREL PLATING OF 0.001 INCHES. PLATED HOLES SHALL NOT BE ROUGH OR IRREGULAR SO AS TO | SOLDERMASK OVER BARE COPPER OR BARE GOLD (BOTH SIDES) TO MEET IPC-SM-840. | IF PRESENT,DO NOT MODIFY SOLDERMASK DEFINED PADS (MASK OPENINGS LESS THAN COPPER PAD) WITHOUT APPROVAL. | MEET THE REQUIREMENTS LISTED IN THE IMPEDANCE TABLE. ANY ADJUSTMENT MADE TO THE DEFINED STACKUP, | UL FLAMMABILITY RATING 94V-0. BOARD MATERIAL & CONSTRUCTION SHALL MEET THE REQUIREMENTS OF UL796/UL796F. | BONDABLE GOLD OVER 100-150 MICRO INCHES OF NICKEL | NICKEL UNDER 30 MICRO-INCHES (.00003') OF GOLD | 0.100 INCH CLEARANCE FROM ALL COPPER FEATURES, | THE STARTING COPPER WEIGHT/THICKNESS CAN VARY AS LONG AS THE FINISHED COPPER | WEIGHT/THICKNESS IS NOT LESS THAN THE SPECIFIED VALUE. | UNLESS OTHERWISE SPECIFIED | HOMOGENOUS MATERIALS IN THIS BOARD SHALL BE COMPLAINT WITH THE EU DIRECTIVE 2002/95/EC | WORKMANSHIP SHALL CONFORM TO IPC-A-600, CLASS 2. | 21.  INTENTIONAL SHORTS: | 17.  FINAL ELECTRICAL TEST TO BE PERFORMED USING PROVIDED IPC-D-356A NETLIST OR ODB++ FORMAT FILE. | 22.  PEMNUTS: | 23.  MANUFACTURER TO ETCH/STAMP WITH PERMANENT NON-CONDUCTIVE INK | ON SECONDARY SIDE UNLESS OTHERWISE SPECIFIED: | 18.  A TIME DOMAIN REFLECTOMETER REPORT (TDR) FOR EACH IMPEDANCE CONTROLLED LAYER & A CERTIFICATE | 19.  IF PRESENT, ALL BLIND/BURIED VIAS WITH AN ASPECT RATIO <1:1 TO BE PLATED SHUT WITH COPPER WHEN | 20.  FOR VIA FILL INFORMATION REFER TO DRILL CHART: | 25. PANELIZATION: | 27.  MINIMUM DESIGN LINE WIDTH IS .XXX INCH. | 28.  MINIMUM DESIGN LINE SPACING IS .XXX INCH. | IS ACCEPTABLE, ALL OTHER INSTANCES MUST BE REPORTED. | IF AN INTENTIONAL SHORT REPORT IS SUPPLIED AND DOES NOT MATCH THE FAB DATA THEN | THE PCB SHALL HAVE A VERIFICATION STAMP. | ( )  NON-CONDUCTIVE EPOXY FILL ALL 0.XXXX INCHES DRILLED VIAS | ( )  COPPER FILL ALL 0.XXXX INCHES DRILLED VIAS | ( ) PEMNUTS TO BE INSTALLED BY FABRICATOR | ( ) PEMNUTS NOT TO BE INSTALLED BY FABRICATOR | ( ) NOT APPLICABLE | USED AS VIA-IN-PAD OR AS A STACKED VIA. BLIND/BURIED VIAS WITH AN ASPECT RATIO >1:1 TO BE FILLED | A. UL CODE-FLAMMABILITY RATING FOR THOSE APPROVED MATERIALS(IF APPLICABLE) | B. DATE CODE | C. LOT NUMBER | D. MANUFACTURER LOGO | BOARDS TO BE SHIPPED IN ARRAY AND KEPT INTACT | PANEL TO BE SUBJECTED TO CUSTOMERS APPROVAL | PANEL SOLDER PASTE STENCIL GERBER TO BE PROVIDED TO ANALOG | CAN'T BE PERFORMED BECAUSE THE TRACE LENGTH IS TOO SHORT ON THE OUTER LAYERS AT THE PIN ESCAPES | ADI APPROVAL IS REQUIRED. | OF COMPLIANCE SHALL BE PROVIDED BY VENDOR AT TIME OF SHIPMENT. INSTANCES WHERE TDR TESTING | WITH NON-CONDUCTIVE EPOXY. | NOTES: | TOOLING: | FINISH: | MATERIAL: | TESTING: | MISCELLANEOUS:
User.18: 08-      -07 | LAYER 2 | L2-GND PLANE
User.19: LAYER 3 | 08-      -08 | 08-      -07 | L2-SIGNAL/GND
User.20: 08-      -08 | L3-SIGNAL/GND
User.21: L5-SIGNAL/GND | 08-      -10
User.27: 1
User.45: 2 | FIGURE | SIZE | 6.0 | 10.0 | 45.0 | 100.0 | 185.0 | PLATED | NON-PLATED | DRILL CHART: TOP to BOTTOM | ALL UNITS ARE IN MILS | QTY | 18 | 394 | 6 | 15 | 4 | TOLERANCE/NOTES
